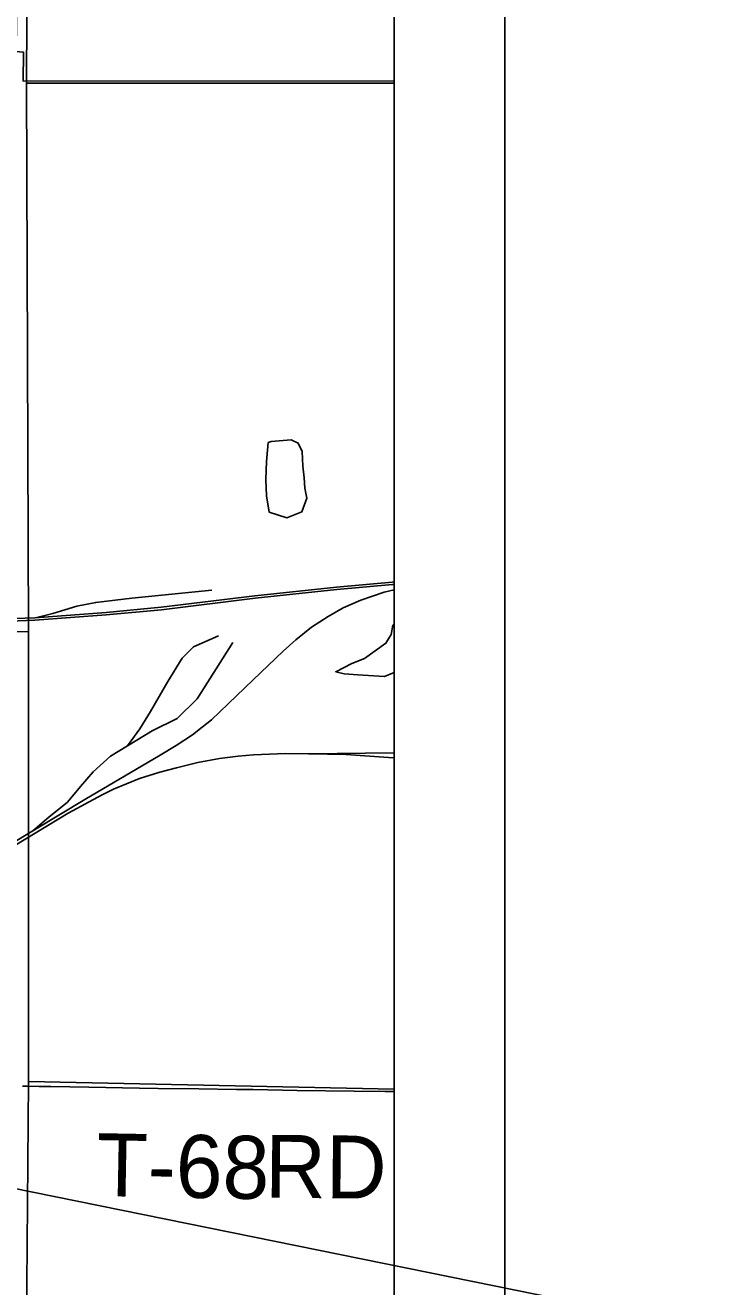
# Model space of a CAD drawing. Extents: x 0 to 34, y 0 to 22.
# Drawn here: x 8.567 to 9.197, y 19.262 to 20.401 of the extents above; entities that cross this region are included whole.
import ezdxf

# ---------------------------------------------------------------- set-up
doc = ezdxf.new("R2010")
doc.units = 0
for name, color, linetype in [('GM_X_Corporation', 7, 'Continuous'), ('GM_X_Minor_Lake', 7, 'Continuous'), ('GM_X_Rail_Line', 7, 'Continuous'), ('GM_X_Township_Road', 7, 'Continuous'), ('GM_X_Township_Road_Text', 7, 'Continuous'), ('SH_Data', 7, 'Continuous'), ('SH_Text', 7, 'Continuous')]:
    doc.layers.add(name, color=color, linetype=linetype)

msp = doc.modelspace()

# ---------------------------------------------------------------- linework, layer by layer
at = {"layer": 'GM_X_Corporation'}
for points in [[(2.1, 14.1), (8.9, 14.1), (8.9, 20.9), (5.8906, 20.9)], [(8.5605, 20.5722), (8.5584, 20.3778), (8.565, 20.3771), (8.5647, 20.351), (8.9, 20.3511), (8.9, 20.9)], [(8.9, 14.3789), (8.9, 20.9)]]:
    msp.add_lwpolyline(points, dxfattribs=at)
for points in [[(7.7961, 20.8998), (8.0431, 20.8969), (8.5706, 20.8869), (8.5677, 20.3491), (8.5695, 19.8537), (7.5413, 19.8609), (7.5417, 20.3812), (7.5405, 20.8943)], [(8.9, 20.349), (8.9, 20.9), (8.5707, 20.9), (8.5706, 20.8869), (8.5677, 20.3491)], [(8.9, 19.4405), (8.9, 20.349), (8.5677, 20.3491), (8.5695, 19.8537), (8.5696, 19.4474)], [(7.5413, 19.8609), (8.5695, 19.8537), (8.5696, 19.4474), (8.5646, 18.8232), (7.5285, 18.8343)], [(8.9, 18.4234), (8.9, 19.4405), (8.5696, 19.4474), (8.5646, 18.8232), (8.5626, 18.4264)]]:
    msp.add_lwpolyline(points, close=True, dxfattribs=at)
at = {"layer": 'GM_X_Minor_Lake'}
msp.add_line((8.8191, 19.9835), (8.8185, 19.9926), dxfattribs=at)
for points in [[(8.8185, 19.9926), (8.8175, 20.0032), (8.8169, 20.0165), (8.8133, 20.0241), (8.8069, 20.0269), (8.7887, 20.0256), (8.7861, 20.0245), (8.7847, 20.0074), (8.7841, 19.9911), (8.7847, 19.9763), (8.7871, 19.9618), (8.8029, 19.9567), (8.8166, 19.9619), (8.8209, 19.9743), (8.8191, 19.9835)], [(8.9, 19.8602), (8.8987, 19.8595), (8.8971, 19.8512), (8.8925, 19.8433), (8.873, 19.8295), (8.8617, 19.8251), (8.8472, 19.8176), (8.8547, 19.8157), (8.8672, 19.8147), (8.8913, 19.8133), (8.9, 19.817)]]:
    msp.add_lwpolyline(points, dxfattribs=at)
at = {"layer": 'GM_X_Rail_Line'}
msp.add_line((8.8224, 19.7433), (8.9, 19.7443), dxfattribs=at)
for points in [[(6.9125, 19.8919), (7.7104, 19.8779), (8.0238, 19.873), (8.0864, 19.8717), (8.3608, 19.8644), (8.4801, 19.8635), (8.5225, 19.8644), (8.5752, 19.8664), (8.6397, 19.8712), (8.6895, 19.8758), (8.7741, 19.8862), (8.8479, 19.894), (8.8982, 19.8986), (8.9, 19.8988)], [(6.9125, 19.8896), (7.7104, 19.8755), (8.0238, 19.8707), (8.0863, 19.8694), (8.3608, 19.862), (8.4802, 19.8611), (8.5226, 19.862), (8.5753, 19.8641), (8.6399, 19.8689), (8.6898, 19.8735), (8.7744, 19.8839), (8.8481, 19.8917), (8.8984, 19.8963), (8.9, 19.8965)], [(8.3458, 19.5368), (8.6204, 19.7022), (8.6886, 19.7422), (8.7029, 19.7509), (8.7177, 19.7607), (8.7265, 19.7674), (8.735, 19.7742), (8.7726, 19.8102), (8.7996, 19.8361), (8.811, 19.8463), (8.8251, 19.8577), (8.8403, 19.8675), (8.8538, 19.8752), (8.8697, 19.8821), (8.8909, 19.8894), (8.9, 19.8916)], [(8.5771, 19.8665), (8.5915, 19.8703), (8.6132, 19.8769), (8.6303, 19.8801), (8.6629, 19.8841), (8.7352, 19.8913)], [(8.659, 19.7507), (8.6703, 19.766), (8.6797, 19.7818), (8.6955, 19.8089), (8.7083, 19.8297), (8.7187, 19.84), (8.7413, 19.8499)], [(8.7542, 19.844), (8.7221, 19.7932), (8.7039, 19.7754), (8.6812, 19.7641), (8.659, 19.7507)], [(8.3458, 19.5368), (8.3728, 19.5489), (8.6055, 19.6898), (8.6362, 19.7063), (8.6465, 19.7115), (8.6699, 19.7211), (8.6883, 19.727), (8.7032, 19.7308), (8.7225, 19.7356), (8.7421, 19.7392), (8.759, 19.7414), (8.7728, 19.7425), (8.8019, 19.7436), (8.8224, 19.7433)], [(8.659, 19.7507), (8.6437, 19.7414), (8.6279, 19.7271), (8.6166, 19.7138), (8.6047, 19.6999), (8.588, 19.6861), (8.5735, 19.6739)], [(8.8224, 19.7433), (8.8565, 19.7427), (8.8947, 19.7402), (8.9, 19.7397)]]:
    msp.add_lwpolyline(points, dxfattribs=at)
at = {"layer": 'GM_X_Township_Road'}
msp.add_lwpolyline([(8.5642, 19.4433), (8.5684, 19.4433), (8.5792, 19.4431), (8.5898, 19.443), (8.6242, 19.4424), (8.6699, 19.4415), (8.6867, 19.4413), (8.7234, 19.441), (8.7576, 19.4404), (8.7725, 19.4402), (8.8123, 19.4394), (8.8638, 19.4388), (8.8918, 19.4384), (8.9, 19.4384)], dxfattribs=at)
at = {"layer": 'SH_Data'}
for p, q in [((9, 21), (9, 14)), ((9, 21), (9, 14)), ((8.9, 20.9), (8.9, 14.1)), ((8.9, 20.9), (8.9, 14.1))]:
    msp.add_line(p, q, dxfattribs=at)
at = {"layer": 'SH_Text'}
msp.add_lwpolyline([(7.0279, 19.6612), (9.327, 18.9498), (9.327, 19.1946)], close=True, dxfattribs=at)

# ---------------------------------------------------------------- texts
at = {"layer": 'GM_X_Township_Road_Text'}
for s, rotation, p in [('T-68', 358.9473, (8.6305, 19.3441)), ('RD', 359.4936, (8.7831, 19.3426))]:
    msp.add_text(s, height=0.05682, rotation=rotation, dxfattribs=at).set_placement(p)

doc.saveas('drawing.dxf')
